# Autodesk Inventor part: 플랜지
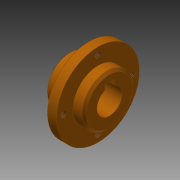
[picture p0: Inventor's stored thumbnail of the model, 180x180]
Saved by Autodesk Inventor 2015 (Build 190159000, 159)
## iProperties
Created: 2019-10
Part Number: 플랜지
Material: 스테인리스강
Document SubType Name: Modeling
Designer: mduedu
Density: 1 g/cm^3
Appearance: 주황색
Author: mduedu
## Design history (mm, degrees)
sketch "스케치1"
  geometry: L1 (0, 0)-(8, 0); L2 (8, 0)-(8, 10); L3 (8, 10)-(0, 10); L4 (0, 10)-(0, 0); L5 (8, 0)-(12, 0); L6 (12, 0)-(12, 18); L7 (12, 18)-(8, 18); L8 (8, 18)-(8, 0); L9 (12, 0)-(17, 0); L10 (17, 0)-(17, 11); L11 (17, 11)-(12, 11); L12 (12, 11)-(12, 0)
  constraints: 24 end point, 6 parallel, 3 horizontal, 3 perpendicular
  dimensions: "d0" = 17 distance between parallel lines of L10 L4; "d2" = 20 diameter of L3 L1; "d3" = 22 diameter of L11 L9; "d4" = 36 diameter of L7 L5; "d5" = 4 distance of L6.end L7.end; "d6" = 5 distance of L10.end L11.end
revolve "회전1" sketch "스케치1" stored, may be unused: angle "d7" = 90 deg
sketch "스케치2"
  geometry: L1 (-2, 5.123)-(2, 5.123); L2 (2, 5.123)-(2, 7.3); L3 (2, 7.3)-(-2, 7.3); L4 (-2, 7.3)-(-2, 5.123); A1 r 5.5 centre (0, 0) between (-2, 5.123) and (2, 5.123); 1 further point
  constraints: 8 end point, 2 parallel, 2 point on circle, 1 centre point, 1 coincident, 1 horizontal, 1 perpendicular
  dimensions: "d8" = 11 diameter of A1; "d10" = 4 distance of L2.end L3.end; "d11" = 7.3 distance from line of L3 point (0, 0)
extrude "돌출1" cut sketch "스케치2" stored distance "d12" = 10; taper "d13" = 0 deg
chamfer "모따기1" distance "d14" = 1; stored, may be unused: second distance "d15" = 2, angle "d16" = 45 deg
chamfer "모따기2" distance "d17" = 1; stored, may be unused: second distance "d18" = 2, angle "d19" = 45 deg
sketch "스케치3" dims "d20" = 30
  geometry: 3 further points
  constraints: 2 vertical alignment, 1 coincident, 2 other
hole "구멍1" sketch "스케치3" at (0, 15) diameter "d21" = 2.459; stored, may be unused: countersink angle "d25" = 90 deg, drill point angle "d27" = 118 deg; dims "d22" = 6, "d23" = 4, "d24" = 2, "d26" = 8
node "솔리드1"
pattern_circular "원형 패턴1" dims angle "d29" = 360 deg
